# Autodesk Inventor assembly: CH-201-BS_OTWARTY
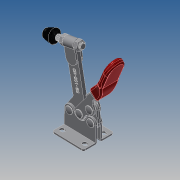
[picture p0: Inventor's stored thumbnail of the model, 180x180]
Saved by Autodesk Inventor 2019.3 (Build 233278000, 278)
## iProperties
Company: ·L?¤¤?
Created: 2010-06
Part Number: CH-201-BS_OTWARTY
Material: Ogólny
Description: STEP AP203
Document SubType Name: Assembly
Designer: CADENGINEERING4
Title: CH-201-BS.STEP
Author: ·L?¥Î?
Revision Number: ANY
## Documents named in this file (9)
- E:\STRONA\Horizontal toggle clamp\CH-201-BS\CH-201-BS_OTWARTY.iam
- E:\STRONA\Horizontal toggle clamp\CH-201-BS\14134-02___.ipt
- E:\STRONA\Horizontal toggle clamp\CH-201-BS\201-B-04___.ipt
- E:\STRONA\Horizontal toggle clamp\CH-201-BS\201-BS-02___.ipt
- E:\STRONA\Horizontal toggle clamp\CH-201-BS\201-B-06___.ipt
- E:\STRONA\Horizontal toggle clamp\CH-201-BS\14134___.ipt
- E:\STRONA\Horizontal toggle clamp\CH-201-BS\BR-142___.ipt
- E:\STRONA\Horizontal toggle clamp\CH-201-BS\201-B___.iam
- E:\STRONA\Horizontal toggle clamp\CH-201-BS\201-B-01___.ipt
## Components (13 placed, 13 different names)
1. 14134-02_??_1 — Równoległe:1, Zestawiające:4, Zestawiające:5
2. 201-B-04_??_2 — Zestawiające:8, Zestawiające:9, Zestawiające:10
3. 201-BS-02_??_3 — Zestawiające:1, Zestawiające:2, Równoległe:2, Zestawiające:19, Zestawiające:22, Zestawiające:23, Zestawiające:24, Zestawiające:25
4. 201-B-06_??_4 — Zestawiające:13, Zestawiające:14
5. 201-B-06_??_5 — Zestawiające:20, Zestawiające:21, Zestawiające:23
6. 14134_??_6 — Równoległe:1, Zestawiające:3, Zestawiające:4, Zestawiające:7
7. 201-B-04_??_7 — Zestawiające:8, Zestawiające:9, Zestawiające:10, Zestawiające:11, Zestawiające:12, Zestawiające:15, Zestawiające:16
8. 14134-02_??_8 — Zestawiające:3, Zestawiające:6
9. BR-142_??_9 — Zestawiające:1, Zestawiające:2, Równoległe:2, Zestawiające:5, Zestawiające:6, Zestawiające:7
10. 201-B_??_10 [sub-assembly] — Zestawiające:15, Zestawiające:16, Zestawiające:17, Zestawiające:18, Zestawiające:19, Zestawiające:20, Zestawiające:21, Zestawiające:22, Przejściowe:1
11. 201-B-06_??_11 — Zestawiające:17, Zestawiające:18
12. 201-B-01_??_12 — Zestawiające:11, Zestawiające:12, Zestawiające:13, Zestawiające:14, Zestawiające:24, Zestawiające:26, Przejściowe:1
13. 201-B-06_??_13 — Zestawiające:25, Zestawiające:26
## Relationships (29: Mate 26, Flush 2, Transitional 1)
- Równoległe:1 [Flush]: 14134-02_??_1 ↔ 14134_??_6
- Zestawiające:1 [Mate]: 201-BS-02_??_3 ↔ BR-142_??_9
- Zestawiające:2 [Mate]: 201-BS-02_??_3 ↔ BR-142_??_9
- Równoległe:2 [Flush]: 201-BS-02_??_3 ↔ BR-142_??_9
- Zestawiające:3 [Mate]: 14134_??_6 ↔ 14134-02_??_8
- Zestawiające:4 [Mate]: 14134-02_??_1 ↔ 14134_??_6
- Zestawiające:5 [Mate]: 14134-02_??_1 ↔ BR-142_??_9
- Zestawiające:6 [Mate]: 14134-02_??_8 ↔ BR-142_??_9
- Zestawiające:7 [Mate]: 14134_??_6 ↔ BR-142_??_9
- Zestawiające:8 [Mate]: 201-B-04_??_2 ↔ 201-B-04_??_7
- Zestawiające:9 [Mate]: 201-B-04_??_2 ↔ 201-B-04_??_7
- Zestawiające:10 [Mate]: 201-B-04_??_2 ↔ 201-B-04_??_7
- Zestawiające:11 [Mate]: 201-B-04_??_7 ↔ 201-B-01_??_12
- Zestawiające:12 [Mate]: 201-B-04_??_7 ↔ 201-B-01_??_12
- Zestawiające:13 [Mate]: 201-B-06_??_4 ↔ 201-B-01_??_12
- Zestawiające:14 [Mate]: 201-B-06_??_4 ↔ 201-B-01_??_12
- Zestawiające:15 [Mate]: 201-B-04_??_7 ↔ 201-B_??_10
- Zestawiające:16 [Mate]: 201-B-04_??_7 ↔ 201-B_??_10
- Zestawiające:17 [Mate]: 201-B_??_10 ↔ 201-B-06_??_11
- Zestawiające:18 [Mate]: 201-B_??_10 ↔ 201-B-06_??_11
- Zestawiające:19 [Mate]: 201-BS-02_??_3 ↔ 201-B_??_10
- Zestawiające:20 [Mate]: 201-B-06_??_5 ↔ 201-B_??_10
- Zestawiające:21 [Mate]: 201-B-06_??_5 ↔ 201-B_??_10
- Zestawiające:22 [Mate]: 201-BS-02_??_3 ↔ 201-B_??_10
- Zestawiające:23 [Mate]: 201-BS-02_??_3 ↔ 201-B-06_??_5
- Zestawiające:24 [Mate]: 201-BS-02_??_3 ↔ 201-B-01_??_12
- Zestawiające:25 [Mate]: 201-BS-02_??_3 ↔ 201-B-06_??_13
- Zestawiające:26 [Mate]: 201-B-01_??_12 ↔ 201-B-06_??_13
- Przejściowe:1 [Transitional]: 201-B_??_10 ↔ 201-B-01_??_12
